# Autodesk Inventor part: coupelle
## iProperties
Shininess: 100.0
Length Units: 11269
Angle Units: 11279
Time Units: 11290
Mass Units: 11283
Length Display Precision: 3
Angle Display Precision: 2
Compacted: True
Created: 2001-12
Part Number: coupelle
Material: Par défaut
Document SubType Name: Modélisation
Designer: pichon
Density: 0.0
Volumn: 0.0
Area: 0.0
PropertySet Name: Model Information
Control State: 0
Master: False
Checked Out: False
Author: pichon
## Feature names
1. Révolution1 [Revolution]
2. Extrusion1
3. Réseau circulaire1 [Circular Pattern]
